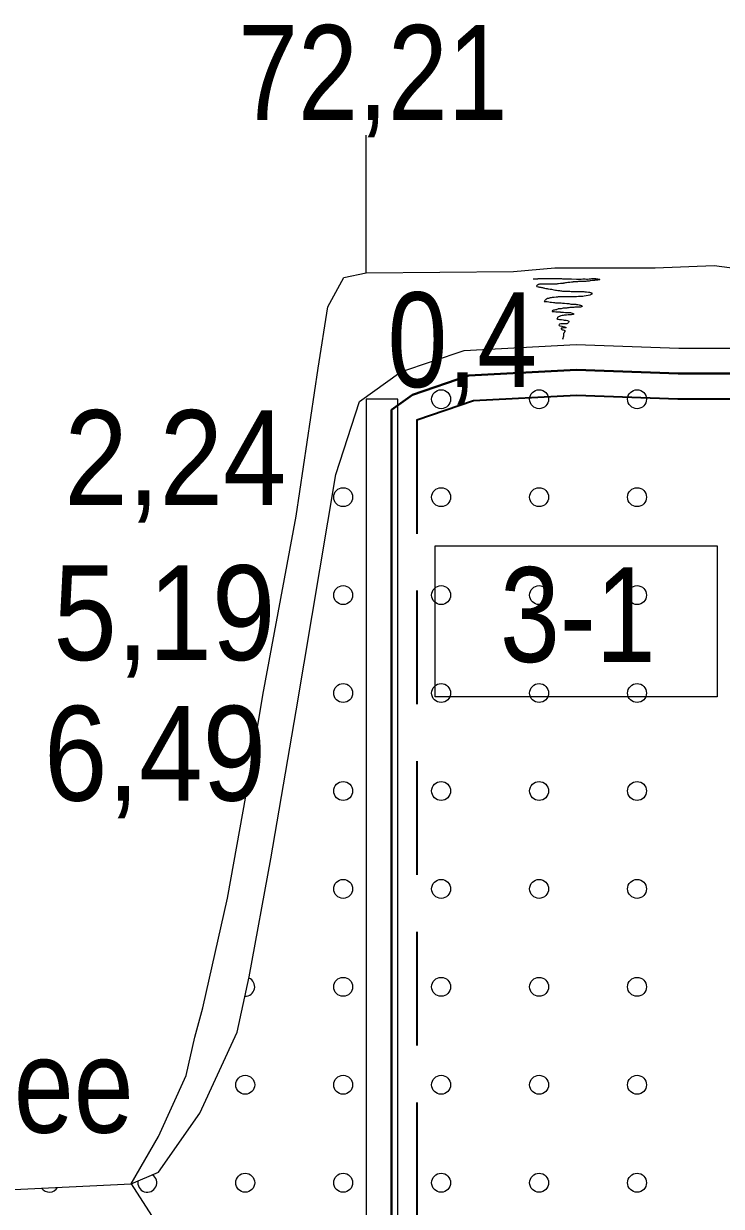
# Model space of a CAD drawing. Extents: x 640121 to 640955, y 6441885 to 6442246.
# Drawn here: x 640163.53 to 640185.61, y 6442170.45 to 6442207.88 of the extents above; entities that cross this region are included whole.
import ezdxf
from ezdxf.enums import TextEntityAlignment as Align

# ---------------------------------------------------------------- set-up
doc = ezdxf.new("R2010")
doc.units = 0
doc.header["$LTSCALE"] = 1.2
doc.linetypes.add('MEDIUM_DASHED', pattern=[4.5, 3, -1.5])
for name, color, linetype, lineweight in [('31', 7, 'Continuous', 13), ('32', 7, 'Continuous', 13), ('33', 7, 'Continuous', 13), ('35', 7, 'Continuous', 35), ('40', 7, 'Continuous', 13), ('43', 7, 'Continuous', 13)]:
    doc.layers.add(name, color=color, linetype=linetype, lineweight=lineweight)

msp = doc.modelspace()

# ---------------------------------------------------------------- linework, layer by layer
at = {"layer": '31'}
msp.add_line((640166.93, 6442171.16), (640167.86, 6442169.72), dxfattribs=at)
for points in [[(640161.69, 6442170.91), (640166.93, 6442171.16), (640167.8, 6442172.66), (640168.67, 6442174.59), (640168.95, 6442175.8), (640169.2, 6442176.73), (640169.98, 6442180.2), (640170.67, 6442184.01), (640171.1, 6442186.63), (640172.16, 6442192.3), (640172.85, 6442196.98), (640173.16, 6442198.92), (640173.66, 6442199.85), (640174.37, 6442200), (640179.03, 6442200.04), (640180.34, 6442200.16), (640183.52, 6442200.16), (640185.39, 6442200.23), (640186.51, 6442200.08), (640187.78, 6442200.08), (640189.79, 6442200.01), (640195.61, 6442199.75), (640205.85, 6442199.5)], [(640166.93, 6442171.16), (640167.8, 6442171.53), (640169.11, 6442173.4), (640170.29, 6442175.96), (640170.67, 6442177.71), (640171.35, 6442181.45), (640172.16, 6442186.13), (640173.41, 6442193.61), (640174.16, 6442195.92), (640175.47, 6442196.86), (640177.47, 6442197.54), (640181.02, 6442197.73), (640184.27, 6442197.61), (640186.26, 6442197.61), (640189.44, 6442197.67), (640193.93, 6442197.86), (640199.4, 6442197.8), (640208.85, 6442198), (640213.83, 6442198.11), (640224.25, 6442197.68), (640233.24, 6442197.62), (640238.51, 6442197.86), (640247.81, 6442197.74)]]:
    msp.add_lwpolyline(points, dxfattribs=at)
at = {"layer": '32', "lineweight": 25}
msp.add_line((640174.37, 6442195.09), (640174.37, 6442080), dxfattribs=at)
at = {"layer": '33'}
msp.add_lwpolyline([(640175.37, 6442170), (640175.37, 6442196), (640174.37, 6442196), (640174.37, 6442170)], close=True, dxfattribs=at)
at = {"layer": '33', "lineweight": 25}
msp.add_lwpolyline([(640176.56, 6442191.36), (640185.48, 6442191.36), (640185.48, 6442186.58), (640176.56, 6442186.58)], close=True, dxfattribs=at)
at = {"layer": '35', "lineweight": 13}
msp.add_line((640174.37, 6442200), (640174.37, 6442204.36), dxfattribs=at)
at = {"layer": '35', "linetype": 'MEDIUM_DASHED'}
msp.add_line((640175.97, 6442195.34), (640175.97, 6442105.93), dxfattribs=at)
at = {"layer": '35', "lineweight": 40}
for points in [[(640175.17, 6442195.66), (640175.84, 6442196.14), (640177.62, 6442196.75), (640181.03, 6442196.93), (640184.25, 6442196.81), (640186.27, 6442196.81), (640189.47, 6442196.87), (640193.95, 6442197.06), (640199.4, 6442197), (640208.87, 6442197.2), (640213.82, 6442197.31), (640224.23, 6442196.88), (640233.26, 6442196.82), (640238.53, 6442197.06), (640247.79, 6442196.94)], [(640175.17, 6442195.66), (640175.17, 6442085.83), (640261.07, 6442089.76)]]:
    msp.add_lwpolyline(points, dxfattribs=at)
at = {"layer": '35', "linetype": 'MEDIUM_DASHED'}
msp.add_lwpolyline([(640175.97, 6442195.34), (640177.77, 6442195.96), (640181.03, 6442196.13), (640184.24, 6442196.01), (640186.28, 6442196.01), (640189.49, 6442196.07), (640193.96, 6442196.26), (640199.41, 6442196.2), (640208.88, 6442196.4), (640213.82, 6442196.51), (640224.21, 6442196.08), (640233.27, 6442196.02), (640238.54, 6442196.26), (640247.76, 6442196.14)], dxfattribs=at)
at = {"layer": '40'}
for points in [[(640179.66, 6442199.81), (640179.69, 6442199.81), (640179.75, 6442199.81), (640179.8, 6442199.81), (640179.81, 6442199.82), (640179.87, 6442199.82), (640179.95, 6442199.82), (640180.11, 6442199.82), (640180.2, 6442199.82), (640180.22, 6442199.82), (640180.23, 6442199.82), (640180.27, 6442199.82), (640180.31, 6442199.82), (640180.37, 6442199.82), (640180.41, 6442199.82), (640180.44, 6442199.82), (640180.48, 6442199.82), (640180.52, 6442199.82), (640180.55, 6442199.82), (640180.59, 6442199.81), (640180.62, 6442199.81), (640180.65, 6442199.81), (640180.7, 6442199.81), (640180.87, 6442199.81), (640181.03, 6442199.8), (640181.07, 6442199.8), (640181.1, 6442199.8), (640181.12, 6442199.8), (640181.15, 6442199.8), (640181.18, 6442199.8), (640181.23, 6442199.81), (640181.25, 6442199.81), (640181.27, 6442199.81), (640181.28, 6442199.81), (640181.3, 6442199.81), (640181.34, 6442199.8), (640181.36, 6442199.8), (640181.38, 6442199.8), (640181.43, 6442199.81), (640181.46, 6442199.81), (640181.49, 6442199.81), (640181.51, 6442199.82), (640181.55, 6442199.82), (640181.57, 6442199.82), (640181.59, 6442199.82), (640181.61, 6442199.82), (640181.63, 6442199.82), (640181.65, 6442199.81), (640181.67, 6442199.81), (640181.69, 6442199.81)], [(640181.69, 6442199.81), (640181.72, 6442199.8), (640181.73, 6442199.8), (640181.76, 6442199.8), (640181.77, 6442199.79), (640181.76, 6442199.78), (640181.76, 6442199.79), (640181.75, 6442199.78), (640181.72, 6442199.78), (640181.69, 6442199.77), (640181.67, 6442199.77), (640181.65, 6442199.77), (640181.63, 6442199.76), (640181.61, 6442199.76), (640181.6, 6442199.75), (640181.57, 6442199.75), (640181.54, 6442199.75), (640181.52, 6442199.75), (640181.46, 6442199.74), (640181.43, 6442199.73), (640181.42, 6442199.73), (640181.39, 6442199.73), (640181.37, 6442199.73), (640181.35, 6442199.73), (640181.32, 6442199.72), (640181.3, 6442199.72), (640181.25, 6442199.72), (640181.22, 6442199.72), (640181.18, 6442199.72), (640181.14, 6442199.72), (640181.11, 6442199.72), (640181.09, 6442199.72), (640181.06, 6442199.71), (640181.03, 6442199.71), (640180.94, 6442199.71), (640180.92, 6442199.71), (640180.91, 6442199.7), (640180.87, 6442199.7), (640180.82, 6442199.69), (640180.78, 6442199.69), (640180.75, 6442199.69), (640180.71, 6442199.68), (640180.68, 6442199.68), (640180.65, 6442199.67), (640180.62, 6442199.67), (640180.61, 6442199.66), (640180.59, 6442199.66), (640180.56, 6442199.66), (640180.54, 6442199.66), (640180.52, 6442199.66), (640180.46, 6442199.65), (640180.43, 6442199.65)], [(640180.43, 6442199.65), (640180.41, 6442199.64), (640180.38, 6442199.64), (640180.37, 6442199.64), (640180.35, 6442199.64), (640180.33, 6442199.64), (640180.31, 6442199.64), (640180.28, 6442199.64), (640180.26, 6442199.64), (640180.22, 6442199.64), (640180.2, 6442199.64), (640180.17, 6442199.64), (640180.16, 6442199.64), (640180.14, 6442199.64), (640180.12, 6442199.64), (640180.1, 6442199.64), (640180.07, 6442199.64), (640180.04, 6442199.64), (640180.02, 6442199.64), (640180, 6442199.64), (640179.97, 6442199.64), (640179.95, 6442199.64), (640179.93, 6442199.64), (640179.91, 6442199.64), (640179.89, 6442199.64), (640179.86, 6442199.64), (640179.84, 6442199.63), (640179.82, 6442199.63), (640179.8, 6442199.62), (640179.79, 6442199.61), (640179.78, 6442199.61), (640179.77, 6442199.6), (640179.76, 6442199.58), (640179.77, 6442199.56), (640179.81, 6442199.55), (640179.84, 6442199.55), (640179.86, 6442199.54), (640179.89, 6442199.54), (640179.9, 6442199.54), (640179.92, 6442199.53), (640179.95, 6442199.53), (640179.97, 6442199.52), (640179.99, 6442199.52), (640180.02, 6442199.51), (640180.06, 6442199.5), (640180.1, 6442199.5), (640180.12, 6442199.49), (640180.14, 6442199.49), (640180.19, 6442199.48), (640180.24, 6442199.48)], [(640180.24, 6442199.48), (640180.31, 6442199.46), (640180.36, 6442199.45), (640180.39, 6442199.45), (640180.44, 6442199.44), (640180.49, 6442199.44), (640180.52, 6442199.43), (640180.55, 6442199.43), (640180.58, 6442199.42), (640180.62, 6442199.42), (640180.65, 6442199.42), (640180.69, 6442199.42), (640180.73, 6442199.42), (640180.77, 6442199.42), (640180.82, 6442199.42), (640180.86, 6442199.41), (640180.89, 6442199.41), (640180.91, 6442199.41), (640180.94, 6442199.41), (640180.98, 6442199.41), (640181.02, 6442199.41), (640181.07, 6442199.41), (640181.11, 6442199.41), (640181.14, 6442199.41), (640181.18, 6442199.41), (640181.2, 6442199.41), (640181.23, 6442199.41), (640181.26, 6442199.41), (640181.29, 6442199.4), (640181.32, 6442199.4), (640181.34, 6442199.4), (640181.41, 6442199.39), (640181.44, 6442199.38), (640181.47, 6442199.37), (640181.49, 6442199.36), (640181.51, 6442199.36), (640181.51, 6442199.34), (640181.51, 6442199.32), (640181.49, 6442199.31), (640181.48, 6442199.31), (640181.47, 6442199.3), (640181.45, 6442199.29), (640181.4, 6442199.28), (640181.33, 6442199.27), (640181.27, 6442199.26), (640181.23, 6442199.25), (640181.18, 6442199.25), (640181.14, 6442199.25), (640181.09, 6442199.25), (640181.03, 6442199.24), (640180.93, 6442199.24), (640180.85, 6442199.24)], [(640180.85, 6442199.24), (640180.8, 6442199.24), (640180.77, 6442199.24), (640180.73, 6442199.24), (640180.7, 6442199.24), (640180.67, 6442199.24), (640180.62, 6442199.24), (640180.58, 6442199.24), (640180.49, 6442199.24), (640180.45, 6442199.24), (640180.43, 6442199.23), (640180.38, 6442199.23), (640180.32, 6442199.22), (640180.26, 6442199.22), (640180.23, 6442199.21), (640180.2, 6442199.21), (640180.19, 6442199.21), (640180.17, 6442199.2), (640180.16, 6442199.2), (640180.14, 6442199.19), (640180.12, 6442199.19), (640180.11, 6442199.18), (640180.08, 6442199.16), (640180.06, 6442199.15), (640180.05, 6442199.13), (640180.04, 6442199.13), (640180.03, 6442199.12), (640180.02, 6442199.1), (640180.01, 6442199.09), (640180.02, 6442199.09), (640180.04, 6442199.09), (640180.07, 6442199.09), (640180.1, 6442199.09), (640180.15, 6442199.08), (640180.19, 6442199.07), (640180.24, 6442199.07), (640180.3, 6442199.06), (640180.33, 6442199.06), (640180.36, 6442199.05), (640180.39, 6442199.05), (640180.47, 6442199.05), (640180.54, 6442199.05), (640180.59, 6442199.04), (640180.65, 6442199.04), (640180.72, 6442199.03), (640180.79, 6442199.03), (640180.85, 6442199.01), (640180.89, 6442199.01), (640180.94, 6442199.01), (640180.98, 6442199.01)], [(640180.98, 6442199.01), (640181.01, 6442199.01), (640181.03, 6442199), (640181.07, 6442198.99), (640181.11, 6442198.98), (640181.13, 6442198.97), (640181.16, 6442198.97), (640181.19, 6442198.96), (640181.2, 6442198.95), (640181.21, 6442198.93), (640181.19, 6442198.92), (640181.18, 6442198.92), (640181.16, 6442198.91), (640181.1, 6442198.91), (640181.07, 6442198.91), (640181.06, 6442198.91), (640181.02, 6442198.91), (640180.98, 6442198.91), (640180.94, 6442198.9), (640180.91, 6442198.9), (640180.89, 6442198.9), (640180.82, 6442198.9), (640180.79, 6442198.89), (640180.77, 6442198.89), (640180.74, 6442198.89), (640180.72, 6442198.88), (640180.69, 6442198.88), (640180.65, 6442198.88), (640180.61, 6442198.88), (640180.57, 6442198.87), (640180.54, 6442198.86), (640180.52, 6442198.86), (640180.5, 6442198.86), (640180.48, 6442198.86), (640180.45, 6442198.86), (640180.44, 6442198.85), (640180.41, 6442198.84), (640180.4, 6442198.83), (640180.38, 6442198.83), (640180.36, 6442198.83), (640180.33, 6442198.82), (640180.3, 6442198.82), (640180.28, 6442198.8), (640180.26, 6442198.79), (640180.26, 6442198.77), (640180.28, 6442198.77), (640180.32, 6442198.77), (640180.37, 6442198.76), (640180.41, 6442198.76), (640180.43, 6442198.76), (640180.48, 6442198.76), (640180.51, 6442198.76)], [(640180.51, 6442198.76), (640180.52, 6442198.75), (640180.54, 6442198.75), (640180.57, 6442198.75), (640180.61, 6442198.75), (640180.62, 6442198.75), (640180.68, 6442198.74), (640180.72, 6442198.74), (640180.74, 6442198.74), (640180.76, 6442198.74), (640180.78, 6442198.74), (640180.81, 6442198.74), (640180.84, 6442198.74), (640180.86, 6442198.73), (640180.89, 6442198.72), (640180.91, 6442198.71), (640180.93, 6442198.71), (640180.93, 6442198.68), (640180.87, 6442198.67), (640180.79, 6442198.67), (640180.76, 6442198.67), (640180.71, 6442198.66), (640180.68, 6442198.66), (640180.64, 6442198.66), (640180.61, 6442198.65), (640180.57, 6442198.65), (640180.53, 6442198.64), (640180.49, 6442198.62), (640180.48, 6442198.61), (640180.46, 6442198.6), (640180.44, 6442198.59), (640180.43, 6442198.58), (640180.43, 6442198.56), (640180.41, 6442198.54), (640180.43, 6442198.53), (640180.45, 6442198.53), (640180.49, 6442198.52), (640180.55, 6442198.52), (640180.61, 6442198.51), (640180.64, 6442198.5), (640180.66, 6442198.5), (640180.7, 6442198.5), (640180.74, 6442198.49), (640180.79, 6442198.47), (640180.79, 6442198.45), (640180.78, 6442198.43), (640180.77, 6442198.42), (640180.74, 6442198.39), (640180.72, 6442198.38), (640180.69, 6442198.38), (640180.65, 6442198.38), (640180.61, 6442198.38), (640180.57, 6442198.38), (640180.53, 6442198.38), (640180.49, 6442198.37), (640180.48, 6442198.35), (640180.47, 6442198.34), (640180.48, 6442198.33), (640180.5, 6442198.32), (640180.56, 6442198.31), (640180.6, 6442198.3), (640180.62, 6442198.29), (640180.65, 6442198.29), (640180.68, 6442198.28), (640180.7, 6442198.27), (640180.69, 6442198.26), (640180.66, 6442198.26), (640180.62, 6442198.26), (640180.58, 6442198.25), (640180.56, 6442198.25), (640180.54, 6442198.25), (640180.54, 6442198.22), (640180.55, 6442198.21), (640180.56, 6442198.2), (640180.58, 6442198.19), (640180.61, 6442198.19), (640180.64, 6442198.18), (640180.66, 6442198.17), (640180.67, 6442198.15), (640180.65, 6442198.14), (640180.65, 6442198.12), (640180.64, 6442198.1), (640180.62, 6442198.09), (640180.62, 6442198.07), (640180.62, 6442198.04), (640180.62, 6442198.02), (640180.62, 6442198.01), (640180.62, 6442197.98), (640180.61, 6442197.97), (640180.61, 6442197.95), (640180.6, 6442197.93), (640180.6, 6442197.9), (640180.6, 6442197.9), (640180.6, 6442197.92)]]:
    msp.add_lwpolyline(points, dxfattribs=at)
at = {"layer": '43'}
for centre in [(640176.744, 6442195.996), (640179.844, 6442195.996), (640182.944, 6442195.996), (640173.644, 6442192.896), (640176.744, 6442192.896), (640179.844, 6442192.896), (640182.944, 6442192.896), (640173.644, 6442189.796), (640176.744, 6442189.796), (640179.844, 6442189.796), (640182.944, 6442189.796), (640173.644, 6442186.696), (640176.744, 6442186.696), (640179.844, 6442186.696), (640182.944, 6442186.696), (640173.644, 6442183.596), (640176.744, 6442183.596), (640179.844, 6442183.596), (640182.944, 6442183.596), (640173.644, 6442180.496), (640176.744, 6442180.496), (640179.844, 6442180.496), (640182.944, 6442180.496), (640173.644, 6442177.396), (640176.744, 6442177.396), (640179.844, 6442177.396), (640182.944, 6442177.396), (640170.544, 6442174.296), (640173.644, 6442174.296), (640176.744, 6442174.296), (640179.844, 6442174.296), (640182.944, 6442174.296), (640170.544, 6442171.196), (640173.644, 6442171.196), (640176.744, 6442171.196), (640179.844, 6442171.196), (640182.944, 6442171.196)]:
    msp.add_circle(centre, 0.3, dxfattribs=at)
for centre, start, end in [((640170.544, 6442177.396), 268.5499, 67.2605), ((640167.444, 6442171.196), 168.6545, 57.7427), ((640164.344, 6442171.196), 214.9779, 330.4747)]:
    msp.add_arc(centre, 0.3, start, end, dxfattribs=at)

# ---------------------------------------------------------------- texts
at = {"layer": '31', "width": 0.85}
msp.add_text('Tee', height=3, dxfattribs=at).set_placement((640164.075, 6442172.78), align=Align.CENTER)
at = {"layer": '32'}
for s, width, p in [('72,21', 0.85, (640174.585, 6442204.84)), ('0,4', 0.85, (640177.415, 6442196.38)), ('2,24', 0.9, (640168.335, 6442192.65)), ('6,49', 0.9, (640167.69, 6442183.29))]:
    msp.add_text(s, height=3, dxfattribs=dict(at, width=width)).set_placement(p, align=Align.CENTER)
at = {"layer": '33'}
for s, width, p in [('5,19', 0.9, (640167.985, 6442187.74)), ('3-1', 0.85, (640181.07, 6442187.68))]:
    msp.add_text(s, height=3, dxfattribs=dict(at, width=width)).set_placement(p, align=Align.CENTER)

doc.saveas('drawing.dxf')
